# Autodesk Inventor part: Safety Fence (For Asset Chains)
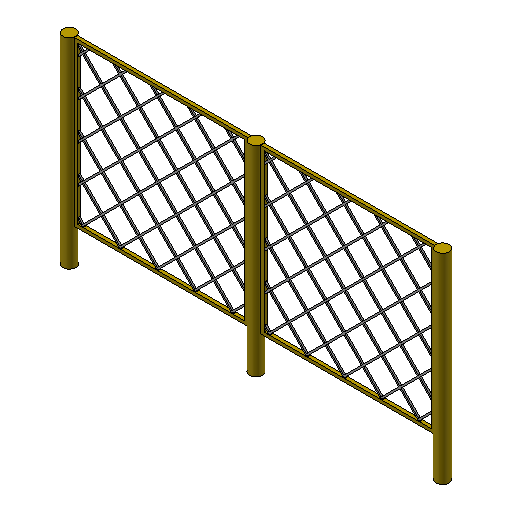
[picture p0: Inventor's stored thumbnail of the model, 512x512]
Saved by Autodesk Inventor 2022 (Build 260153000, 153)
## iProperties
ConnectorClass: SafetyEquipment
family_type: SafetyFence
Created: 2009-11
Part Number: Safety Fence (For Asset Chains)
Document SubType Name: Modeling
Designer: Autodesk, Inc.
Density: 1 g/cm^3
Material: 一般
Appearance: 既定
Sheet Metal Rule: Default
Key Parameters: Height=1524.000 mm;BottomHeight=279.000 mm;Number=2.000 ul;SectionLength=2939.000 mm
Author: Autodesk, Inc.
Title: Safety Fence (For Asset Chains)
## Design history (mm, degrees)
sketch "Sketch1"
  geometry: L1 (0, -622.5)-(1321, -622.5); L2 (1321, -622.5)-(1321, 622.5); L3 (1321, 622.5)-(0, 622.5); L4 (0, 622.5)-(0, -622.5); L5 (25, -597.5)-(1296, -597.5); L6 (1296, -597.5)-(1296, 597.5); L7 (1296, 597.5)-(25, 597.5); L8 (25, 597.5)-(25, -597.5); 5 further points
  constraints: 16 end point, 4 midpoint, 4 parallel, 2 coincident, 2 horizontal, 2 perpendicular, 1 horizontal alignment, 1 vertical alignment
  dimensions: "d0" = 1245 distance of L3.end L1.start (= Height1); "d1" = 1195 distance of L7.end L5.start (= Height1 - 2 x WidthOfBranch); "d2" = 1321 distance of L1.start L1.end (= SectionLength_1); "d3" = 1271 distance of L5.start L5.end (= d2 - 2 x WidthOfBranch)
extrude "Extrusion1" new body sketch "Sketch1" stored distance "d4" = 25.4; taper "d5" = 0 deg
sketch "Sketch2"
  geometry: L1 (50.4, 597.5)-(-1448.6, -901.5); L2 (68.361, 597.5)-(-1430.639, -901.5); L3 (-1448.6, -901.5)-(-1430.639, -901.5); L4 (50.4, 597.5)-(68.361, 597.5); L5 (25, 597.5)-(1296, 597.5) reference; L6 (25, -597.5)-(25, 597.5) reference; L7 (1296, 597.5)-(25, 597.5) reference; 2 further points
  constraints: 8 end point, 2 midpoint, 2 parallel, 1 horizontal alignment
  dimensions: "d10" = 12.7 distance between parallel lines of L1 L2; "d20" = 45 deg angle of L5 L1; "d21" = 25.4 distance from line of L6 L1.start; "d51" = 1499 distance between parallel lines of L4 L3 (derived)
extrude "Extrusion2" join sketch "Sketch2" stored distance "d7" = 12.7; taper "d8" = 0 deg
sketch "Sketch3"
  geometry: L1 (-1379.839, 883.539)-(101.2, -597.5); L2 (-1379.839, 901.5)-(119.161, -597.5); L3 (101.2, -597.5)-(119.161, -597.5); L4 (-1379.839, 883.539)-(-1379.839, 901.5); L5 (1296, -597.5)-(25, -597.5) reference; L6 (25, -597.5)-(25, 597.5) reference; 2 further points
  constraints: 8 end point, 2 midpoint, 1 horizontal alignment, 1 parallel, 1 perpendicular
  dimensions: "d13" = 12.7 distance between parallel lines of L1 L2; "d22" = 45 deg angle of L5 L1; "d23" = 76.2 distance of L5.end L1.end; "d24" = 1499 distance from line of L3 L2.start (derived)
extrude "Extrusion3" join sketch "Sketch3" stored distance "d14" = 12.7; taper "d15" = 0 deg
pattern_linear "Rectangular Pattern1" dims "d16" = 113.8 (derived), "d18" = 2845 (derived)
sketch "Sketch4"
  geometry: L1 (25, 597.5)-(25, -597.5) reference; L2 (25, -597.5)-(1296, -597.5) reference; L3 (1296, -597.5)-(1296, 597.5) reference; L4 (1296, 597.5)-(25, 597.5) reference; L5 (1321, -622.5)-(1321, 622.5) reference; L6 (0, -622.5)-(1321, -622.5) reference; L7 (0, 622.5)-(0, -622.5) reference; L8 (1321, 622.5)-(0, 622.5) reference; 1 further point
extrude "Extrusion4" sketch "Sketch4" stored distance "d25" = 127; taper "d26" = 0 deg
pattern_linear "Rectangular Pattern2"
pattern_linear "Rectangular Pattern3" dims "d50" = 1420 (computed from SectionLength_1)
workplane "Work Plane1"
workplane "Work Plane3"
workpoint "Work Point1"
  workaxis "Work Axis3"
workpoint "Work Point2"
workpoint "Work Point3"
node "Landing Surface"
node "Connector1"
node "Connector2"
workpoint "Work Point9"
node "Insertion Point1"
body "Solid1"
sketch "Sketch9" dims "d42" = 99 (= Diameter)
  geometry: L1 (0, 0)-(0, -25.4) reference; 3 further points
  constraints: 2 horizontal alignment, 1 midpoint, 2 other
extrude "Extrusion5" join sketch "Sketch9" distance "d43" = 1524 (derived); taper "d44" = 0 deg
sketch "Sketch10"
  geometry: L1 (1321, -25.4)-(1321, 0) reference; C1 r 49.5 at (1370.5, -12.7); 1 further point
  constraints: 1 centre point, 1 horizontal alignment, 1 midpoint, 1 tangent
  dimensions: "d45" = 99 diameter of C1 (= Diameter)
extrude "Extrusion6" join sketch "Sketch10" distance "d46" = 1524 (derived); taper "d47" = 0 deg
node "Projected Loop1"
workplane "Work Plane4"
feature "Pattern of Solid1:23"
body "Solid24"
other parameters: "SectionLength_1" = 1321 [user parameter; used in 6 equation terms], "WidthOfBranch" = 25 [user parameter; used in 4 equation terms], "Diameter" = 99 [user parameter; used in 2 equation terms], "Height1" = 1245 [user parameter; used in 3 equation terms], "d52" = 2939 (derived), "Thickness" = 3.048 (derived), "KFactor" = 4.4, "BendRadius" = 3.048 (= Thickness), "BendReliefWidth" = 3.048 (= Thickness), "BendReliefDepth" = 1.524 (= 0.5 x Thickness), "CornerReliefSize" = 12.192 (= 4 x Thickness), "SeamGap" = 0.01, "MinimumRemnant" = 6.096 (= 2 x Thickness), "TransitionRadius" = 3.048 (= BendRadius), "JacobiRadiusSize" = 3.048 (= Thickness), "GapSize" = 3.048 (= Thickness), "d73" = -99, "d74" = 0, "d75" = 0, "d76" = -90 deg, "d77" = 0, "d78" = -180 deg, "d80" = 0, "d81" = 0, "d82" = -90 deg, "d83" = 0, "d84" = 0
